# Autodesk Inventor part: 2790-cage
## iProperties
Author: Administrator
Shininess: 64.0
Angle Display Precision: 2
Document Length Units: 11272
Document Angle Units: 11286
Document Time Units: 11279
Document Mass Units: 11290
Document Length Units Precision: 3
Document Angle Units Precision: 2
Compacted: True
PropertySet Name: _Private Model Information
Created: 2002-03
Part Number: 2790-cage
Material: ASTM A36 HRS
Document SubType Name: Modeling
Designer: Administrator
Control State: 0
Master: False
Checked Out: False
PropertySet Name: Design Tracking Control
Density: 0.0
Volumn: 0.0
Area: 0.0
PropertySet Name: Model Information
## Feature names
1. Revolution1
2. Extrusion1
3. Circular Pattern1
